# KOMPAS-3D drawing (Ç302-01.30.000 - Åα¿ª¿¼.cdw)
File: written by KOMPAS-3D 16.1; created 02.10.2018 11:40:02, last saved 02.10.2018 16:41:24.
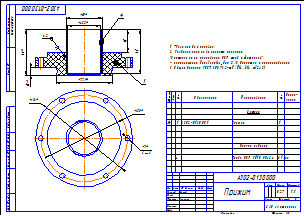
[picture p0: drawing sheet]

Sheet 1: A3, landscape

Title block, sheet 1: name: Прижим; designation: А302-01.30.000; mass: 0,27; scale: 1:1; sheets: 1; organisation: ЗАО «Астерион»; sheet format: A3; stored path: \\192.168.87.28\Konstructor_doc\Мембранные насосы\Мембранный электропривод\А302-00.00.000 - ASTRA-302 (МЭ200)\3Д ПВХ\А302-01.30.000 - Прижим.cdw; drawn by: Милов; technical control: Лучихин

Views: Вид 1, Местный разрез 1, Вид:1, Проекционный вид 2
Referenced files in \\192.168.87.28\Konstructor_doc\Мембранные насосы\Мембранный электропривод\А302-00.00.000 - ASTRA-302 (МЭ200)\3Д ПВХ\Отработка\: Труба ПВХ PN10 50х2,4.m3d
Referenced files in \\192.168.87.28\Konstructor_doc\Мембранные насосы\Мембранный электропривод\А302-00.00.000 - ASTRA-302 (МЭ200)\3Д ПВХ\: А302-01.30.001 - Прижим.m3d, А302-01.30.000 - Прижим.a3d
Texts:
  *Размеры для справок.
  Разделку кромок выполнить согласно:
  "Инструкция по склеиванию ПВХ труб и фитингов".
  - расположение Konstructor_doc Z:\5 Оснастка и приспособления
  Общие допуски ГОСТ 30893.2-mK (H14, h14,  t2/2).
  Труба ПВХ PN10 50х2,4
Dimensions and other numbers on the sheet: 61; 31; 2; 63; 77,9; 10; 50; 45,2; 1; 4; 134; 120; 7; 6 отв.; 1:1; 0,27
